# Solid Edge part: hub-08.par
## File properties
Author: nakano
Template: iso metric part.par
Last saved by: nakano
Revision: 4
Application: Solid Edge
Density: 2404.88656826122 kg/m^3
Accuracy: 0.990
Username: nakano
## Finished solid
Body 1: solid body, 14 faces, 20 edges, 0 vertices.
  Faces by surface: cylinder 10, plane 4
  Edges by curve: circle 16, intersection 4
Bounding box of the edges (mm): 23.800 x 16.662 x 23.800, from (-11.8999, 0, -11.8999) to (11.8999, 16.6624, 11.8999).
Cylindrical faces by radius (mm): R1.1938 x6, R2.3876 x1, R3.9243 x1, R5.3975 x1, R11.8999 x1
Planar faces by outward normal: +y 2, -y 2
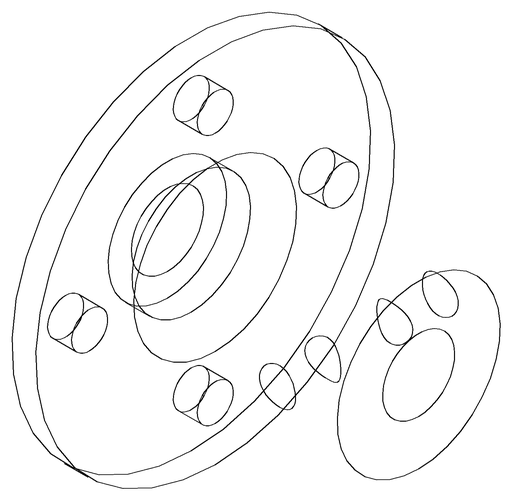
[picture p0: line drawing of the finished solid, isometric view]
